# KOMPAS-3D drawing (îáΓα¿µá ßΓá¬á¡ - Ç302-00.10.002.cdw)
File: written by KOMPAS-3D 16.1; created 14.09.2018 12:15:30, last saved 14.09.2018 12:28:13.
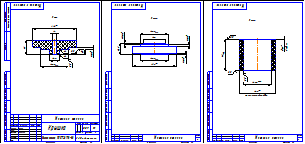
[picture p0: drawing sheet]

Sheets 1-3: A4, portrait

Title block, sheet 1: name: Крышка; designation: Матрица стакан; material: Полипропилен  ГОСТ 26996-86; mass: 0,09; scale: 1:1; sheet number: 1; sheets: 3; organisation: ЗАО «Астерион»; sheet format: A4; stored path: Z:\Мембранные насосы\Мембранный электропривод\А302-00.00.000 - ASTRA-302 (МЭ200)\3Д\Доработка\Матрица стакан - А302-00.10.002.cdw; drawn by: Милов; technical control: Лучихин
Title block, sheet 2: sheet number: 2
Title block, sheet 3: sheet number: 3

Views: Вид 1, Местный разрез 1, Спереди, Проекционный вид 2, Вид 3, Вид 4, Сверху, Проекционный вид 5
Referenced files in Z:\Мембранные насосы\Мембранный электропривод\А302-00.00.000 - ASTRA-302 (МЭ200)\3Д\Доработка\: Матрица стакан Крышка.m3d, Матрица стакан Заглушка.m3d, Матрица стакан обечайка.m3d
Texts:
  Труба полип. ф75 PN20
  А302-00.10.002 - Стакан
  Обечайка
  Заглушка
Dimensions and other numbers on the sheet: 57,7; 20; 8; 90; 12; 3±0,1; 30; 2,5; 1 шт.; 47; 3,5±0,1; 24,5; 1; 2 фаски; 65; 75; 1:1; 0,09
